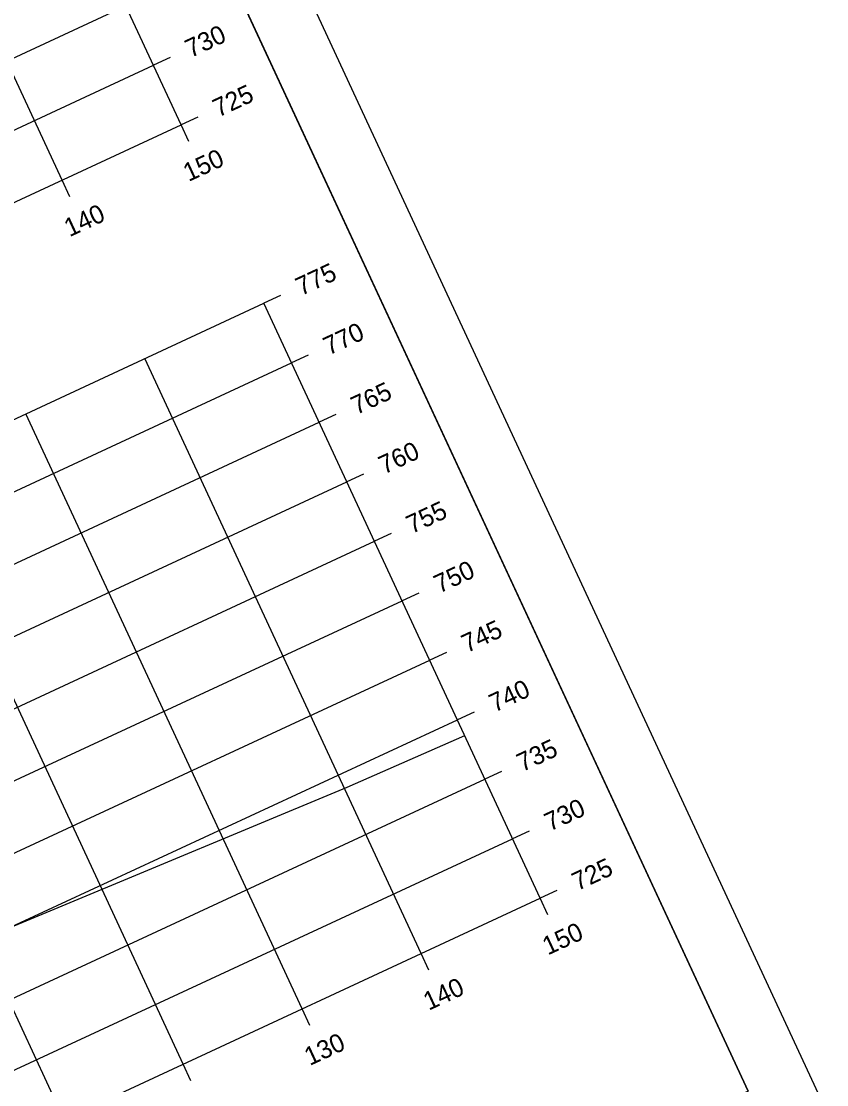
# Model space of a CAD drawing. Extents: x 1354696 to 1366163, y 660729 to 670380.
# Drawn here: x 1358423.4 to 1358484.8, y 665685 to 665766.1 of the extents above; entities that cross this region are included whole.
import ezdxf

# ---------------------------------------------------------------- set-up
doc = ezdxf.new("R2010")
doc.units = 0
for name, color, linetype in [('R_Axis', 7, 'Continuous'), ('R_Axis Annot', 7, 'Continuous'), ('R_Border', 7, 'Continuous'), ('R_Exist Surface', 7, 'Continuous'), ('R_Grid', 7, 'Continuous'), ('R_No Plot', 7, 'Continuous')]:
    doc.layers.add(name, color=color, linetype=linetype)

msp = doc.modelspace()

# ---------------------------------------------------------------- linework, layer by layer
at = {"layer": 'R_Axis'}
for p, q in [((1358435.573, 665758.208), (1358414.518, 665803.559)), ((1358434.737, 665763.333), (1358433.468, 665762.743)), ((1358436.843, 665758.798), (1358435.573, 665758.208)), ((1358163.469, 665631.878), (1358435.573, 665758.208)), ((1358436.163, 665756.939), (1358435.573, 665758.208)), ((1358427.093, 665752.728), (1358426.503, 665753.997)), ((1358443.159, 665745.193), (1358441.89, 665744.603)), ((1358462.945, 665699.253), (1358441.89, 665744.603)), ((1358445.265, 665740.658), (1358443.995, 665740.068)), ((1358447.37, 665736.123), (1358446.101, 665735.533)), ((1358449.476, 665731.588), (1358448.206, 665730.998)), ((1358451.581, 665727.052), (1358450.312, 665726.463)), ((1358453.687, 665722.517), (1358452.417, 665721.928)), ((1358455.793, 665717.982), (1358454.523, 665717.393)), ((1358457.898, 665713.447), (1358456.628, 665712.858)), ((1358460.004, 665708.912), (1358458.734, 665708.323)), ((1358462.109, 665704.377), (1358460.839, 665703.788)), ((1358190.841, 665572.922), (1358462.945, 665699.253)), ((1358464.215, 665699.842), (1358462.945, 665699.253)), ((1358463.534, 665697.983), (1358462.945, 665699.253)), ((1358454.464, 665693.772), (1358453.875, 665695.042)), ((1358445.394, 665689.561), (1358444.804, 665690.831)), ((1358436.324, 665685.35), (1358435.734, 665686.619))]:
    msp.add_line(p, q, dxfattribs=at)
at = {"layer": 'R_Border'}
msp.add_line((1358478.786, 665684.557), (1358392.267, 665870.912), dxfattribs=at)
at = {"layer": 'R_Exist Surface'}
msp.add_lwpolyline([(1358410.895, 665692.164), (1358425.898, 665698.43), (1358448.234, 665707.716), (1358457.189, 665711.649)], dxfattribs=at)
at = {"layer": 'R_Grid'}
for p, q in [((1358435.573, 665758.208), (1358414.518, 665803.559)), ((1358426.503, 665753.997), (1358405.448, 665799.348)), ((1358159.258, 665640.948), (1358431.362, 665767.279)), ((1358161.364, 665636.413), (1358433.468, 665762.743)), ((1358163.469, 665631.878), (1358435.573, 665758.208)), ((1358169.786, 665618.273), (1358441.89, 665744.603)), ((1358462.945, 665699.253), (1358441.89, 665744.603)), ((1358171.891, 665613.738), (1358443.995, 665740.068)), ((1358453.875, 665695.042), (1358432.819, 665740.392)), ((1358444.804, 665690.831), (1358423.749, 665736.181)), ((1358173.997, 665609.203), (1358446.101, 665735.533)), ((1358435.734, 665686.619), (1358414.679, 665731.97)), ((1358176.102, 665604.667), (1358448.206, 665730.998)), ((1358426.664, 665682.408), (1358405.609, 665727.759)), ((1358178.208, 665600.132), (1358450.312, 665726.463)), ((1358180.313, 665595.597), (1358452.417, 665721.928)), ((1358182.419, 665591.062), (1358454.523, 665717.393)), ((1358184.524, 665586.527), (1358456.628, 665712.858)), ((1358186.63, 665581.992), (1358458.734, 665708.323)), ((1358188.735, 665577.457), (1358460.839, 665703.788)), ((1358190.841, 665572.922), (1358462.945, 665699.253))]:
    msp.add_line(p, q, dxfattribs=at)
at = {"layer": 'R_No Plot'}
for points in [[(1358092.593, 665736.076), (1358394.937, 665876.446), (1358484.774, 665682.946), (1358182.43, 665542.576)], [(1358317.656, 665836.272), (1358335.451, 665844.534), (1358339.612, 665835.573), (1358354.226, 665842.358), (1358375.268, 665852.127), (1358387.234, 665826.639), (1358408.284, 665836.412), (1358478.786, 665684.557), (1358192.007, 665551.413), (1358105.487, 665737.768)]]:
    msp.add_lwpolyline(points, close=True, dxfattribs=at)

# ---------------------------------------------------------------- texts
at = {"layer": 'R_Axis Annot'}
for s, p in [('730', (1358436.302, 665763.288)), ('725', (1358438.408, 665758.753)), ('150', (1358436.147, 665753.844)), ('140', (1358427.077, 665749.633)), ('775', (1358444.724, 665745.147)), ('770', (1358446.83, 665740.612)), ('765', (1358448.935, 665736.077)), ('760', (1358451.041, 665731.542)), ('755', (1358453.146, 665727.007)), ('750', (1358455.252, 665722.472)), ('745', (1358457.357, 665717.937)), ('740', (1358459.463, 665713.402)), ('735', (1358461.568, 665708.867)), ('730', (1358463.674, 665704.332)), ('725', (1358465.779, 665699.797)), ('150', (1358463.519, 665694.888)), ('140', (1358454.448, 665690.677)), ('130', (1358445.378, 665686.466))]:
    msp.add_text(s, height=1.4, rotation=24.90417, dxfattribs=at).set_placement(p)

doc.saveas('drawing.dxf')
